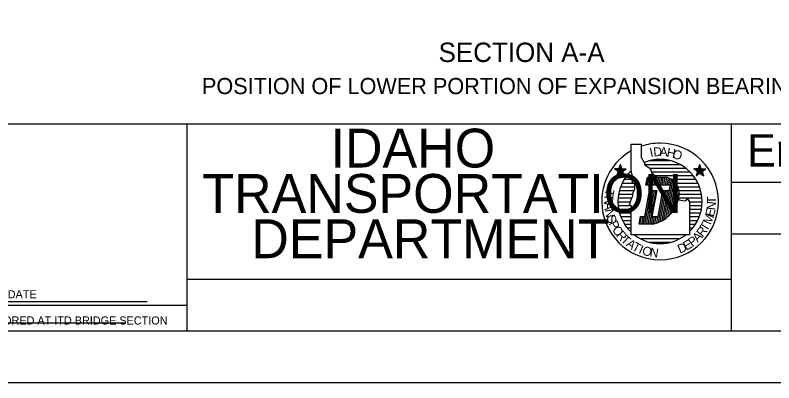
# Model space of a CAD drawing. Extents: x 0 to 22.7, y 0 to 15.7.
# Drawn here: x 8.228 to 13.107, y 0 to 2.366 of the extents above; entities that cross this region are included whole.
import ezdxf

# ---------------------------------------------------------------- set-up
doc = ezdxf.new("R2010")
doc.units = 0
for name, color, linetype in [('BORDER_ANNO_Cutsheet', 7, 'Continuous'), ('BRDG_ANNO_Anno-Large-Print', 7, 'Continuous'), ('BRDG_ANNO_Anno-Sheet', 7, 'Continuous'), ('BRDG_ANNO_Anno-Small-Print', 7, 'Continuous'), ('BRDG_ANNO_General-Notes', 7, 'Continuous')]:
    doc.layers.add(name, color=color, linetype=linetype)

msp = doc.modelspace()

# ---------------------------------------------------------------- linework, layer by layer
at = {"layer": 'BORDER_ANNO_Cutsheet'}
msp.add_lwpolyline([(0, 14.6667), (22.6667, 14.6667), (22.6667, 0), (0, 0)], close=True, dxfattribs=at)
at = {"layer": 'BRDG_ANNO_Anno-Large-Print'}
msp.add_line((7.9329, 0.3871), (8.9371, 0.3871), dxfattribs=at)
at = {"layer": 'BRDG_ANNO_Anno-Sheet'}
for p, q in [((1, 1.6667), (12.8333, 1.6667)), ((9.3333, 0.3333), (9.3333, 1.6667)), ((12.8333, 0.3333), (12.8333, 1.6667)), ((12.8333, 1.6667), (22.3333, 1.6667)), ((12.1896, 1.3617), (12.1896, 1.5354)), ((12.1896, 1.5354), (12.2554, 1.5354)), ((12.2554, 1.4487), (12.2554, 1.5354)), ((12.2554, 1.4487), (12.2729, 1.4175)), ((12.2729, 1.4175), (12.2762, 1.4033)), ((12.31, 1.4296), (12.4387, 1.4296)), ((12.1342, 1.36), (12.0817, 1.3771)), ((12.1104, 1.3771), (12.0817, 1.3771)), ((12.105, 1.36), (12.0817, 1.3771)), ((12.1288, 1.3771), (12.0958, 1.3321)), ((12.105, 1.36), (12.1579, 1.3771)), ((12.1104, 1.3771), (12.1196, 1.4046)), ((12.1104, 1.3771), (12.1433, 1.3321)), ((12.1196, 1.3492), (12.1196, 1.4046)), ((12.1288, 1.3771), (12.1196, 1.4046)), ((12.1288, 1.3771), (12.1579, 1.3771)), ((12.1342, 1.36), (12.1579, 1.3771)), ((12.2762, 1.4033), (12.3108, 1.3792)), ((12.2779, 1.4054), (12.5004, 1.4054)), ((12.31, 1.3817), (12.5379, 1.3817)), ((12.3108, 1.3792), (12.3217, 1.3513)), ((12.645, 1.36), (12.5921, 1.3771)), ((12.6158, 1.36), (12.5921, 1.3771)), ((12.6212, 1.3771), (12.5921, 1.3771)), ((12.6396, 1.3771), (12.6067, 1.3321)), ((12.6158, 1.36), (12.6683, 1.3771)), ((12.6212, 1.3771), (12.6304, 1.4046)), ((12.6212, 1.3771), (12.6542, 1.3321)), ((12.6304, 1.3492), (12.6304, 1.4046)), ((12.6396, 1.3771), (12.6304, 1.4046)), ((12.6396, 1.3771), (12.6683, 1.3771)), ((12.645, 1.36), (12.6683, 1.3771)), ((12.105, 1.36), (12.0958, 1.3321)), ((12.1196, 1.3492), (12.0958, 1.3321)), ((12.1196, 1.3492), (12.1433, 1.3321)), ((12.1342, 1.36), (12.1433, 1.3321)), ((12.1612, 1.3337), (12.1958, 1.3337)), ((12.1829, 1.3575), (12.1908, 1.3575)), ((12.1962, 1.3375), (12.1896, 1.3617)), ((12.1962, 1.3167), (12.1962, 1.3375)), ((12.2833, 1.2712), (12.2937, 1.3237)), ((12.2929, 1.2712), (12.3025, 1.3237)), ((12.2937, 1.3237), (12.4083, 1.3237)), ((12.3033, 1.2712), (12.3133, 1.3237)), ((12.3142, 1.2712), (12.3238, 1.3237)), ((12.3192, 1.3575), (12.5671, 1.3575)), ((12.3217, 1.3513), (12.3562, 1.3237)), ((12.3246, 1.2712), (12.3346, 1.3237)), ((12.335, 1.2712), (12.345, 1.3237)), ((12.3438, 1.3337), (12.5883, 1.3337)), ((12.3458, 1.2712), (12.3554, 1.3237)), ((12.3562, 1.2712), (12.3662, 1.3237)), ((12.3671, 1.2712), (12.3767, 1.3237)), ((12.3775, 1.2712), (12.3875, 1.3237)), ((12.3883, 1.2712), (12.3979, 1.3237)), ((12.3987, 1.2712), (12.4087, 1.3237)), ((12.4092, 1.2712), (12.4187, 1.3208)), ((12.42, 1.2712), (12.4287, 1.3179)), ((12.6158, 1.36), (12.6067, 1.3321)), ((12.6304, 1.3492), (12.6067, 1.3321)), ((12.6304, 1.3492), (12.6542, 1.3321)), ((12.645, 1.36), (12.6542, 1.3321)), ((12.1312, 1.2854), (12.1988, 1.2854)), ((12.1446, 1.3096), (12.195, 1.3096)), ((12.1962, 1.2992), (12.1962, 1.3167)), ((12.2, 1.2854), (12.1962, 1.2992)), ((12.2137, 1.2783), (12.2, 1.2854)), ((12.2137, 1.2608), (12.2137, 1.2783)), ((12.4408, 1.2712), (12.2833, 1.2712)), ((12.3996, 1.0496), (12.4479, 1.3079)), ((12.4117, 1.0571), (12.4575, 1.3013)), ((12.4242, 1.0671), (12.4662, 1.2925)), ((12.4304, 1.2712), (12.4383, 1.3133)), ((12.4346, 1.2367), (12.4408, 1.2712)), ((12.4371, 1.0792), (12.475, 1.2829)), ((12.4458, 1.3096), (12.605, 1.3096)), ((12.4504, 1.0933), (12.4833, 1.2708)), ((12.4733, 1.2854), (12.6183, 1.2854)), ((12.8333, 1.2917), (14.8333, 1.2917)), ((12.1137, 1.2375), (12.2075, 1.2375)), ((12.1208, 1.2617), (12.2125, 1.2617)), ((12.2, 1.2192), (12.2067, 1.2333)), ((12.2067, 1.2333), (12.2137, 1.2504)), ((12.2137, 1.2504), (12.2137, 1.2608)), ((12.2762, 1.07), (12.3075, 1.2367)), ((12.2775, 1.0212), (12.3179, 1.2367)), ((12.2883, 1.0212), (12.3287, 1.2367)), ((12.2988, 1.0212), (12.3392, 1.2367)), ((12.3075, 1.2367), (12.3533, 1.2367)), ((12.3096, 1.0212), (12.35, 1.2367)), ((12.3533, 1.2367), (12.3221, 1.07)), ((12.3625, 1.07), (12.3937, 1.2367)), ((12.3646, 1.0317), (12.4029, 1.2367)), ((12.3758, 1.0367), (12.4133, 1.2367)), ((12.3875, 1.0421), (12.4242, 1.2367)), ((12.3937, 1.2367), (12.4346, 1.2367)), ((12.4646, 1.1125), (12.4912, 1.2546)), ((12.4812, 1.145), (12.4971, 1.23)), ((12.4883, 1.2617), (12.6288, 1.2617)), ((12.4962, 1.2375), (12.6363, 1.2375)), ((12.105, 1.1896), (12.1937, 1.1896)), ((12.1083, 1.2137), (12.1988, 1.2137)), ((12.1858, 1.1671), (12.1896, 1.1812)), ((12.1896, 1.1812), (12.2, 1.2021)), ((12.2, 1.2021), (12.2, 1.2192)), ((12.4938, 1.185), (12.4987, 1.1775)), ((12.495, 1.1896), (12.645, 1.1896)), ((12.4983, 1.2137), (12.6417, 1.2137)), ((12.4987, 1.1775), (12.5196, 1.1742)), ((12.5196, 1.1742), (12.5404, 1.1708)), ((12.5404, 1.1708), (12.5508, 1.1846)), ((12.5508, 1.1846), (12.5646, 1.1638)), ((12.1042, 1.1654), (12.185, 1.1654)), ((12.1054, 1.1417), (12.1875, 1.1417)), ((12.1792, 1.15), (12.1858, 1.1671)), ((12.1896, 1.1396), (12.1792, 1.15)), ((12.1962, 1.1292), (12.1896, 1.1396)), ((12.2, 1.1221), (12.1962, 1.1292)), ((12.5633, 1.1654), (12.6458, 1.1654)), ((12.5646, 1.1638), (12.5646, 0.9517)), ((12.565, 1.1417), (12.6446, 1.1417)), ((12.1087, 1.1175), (12.1988, 1.1175)), ((12.1142, 1.0938), (12.1892, 1.0938)), ((12.1896, 1.1013), (12.2, 1.1117)), ((12.1896, 0.9517), (12.1896, 1.1013)), ((12.2, 1.1117), (12.2, 1.1221)), ((12.5646, 1.1175), (12.6412, 1.1175)), ((12.5646, 1.0938), (12.6358, 1.0938)), ((12.1225, 1.0696), (12.1883, 1.0696)), ((12.1329, 1.0454), (12.1883, 1.0454)), ((12.2396, 1.0212), (12.2487, 1.07)), ((12.2458, 1.0212), (12.255, 1.07)), ((12.2487, 1.07), (12.2762, 1.07)), ((12.2567, 1.0212), (12.2658, 1.07)), ((12.2671, 1.0212), (12.2762, 1.07)), ((12.32, 1.0212), (12.3292, 1.07)), ((12.3221, 1.07), (12.3625, 1.07)), ((12.3308, 1.0217), (12.34, 1.07)), ((12.3421, 1.0246), (12.3504, 1.07)), ((12.3533, 1.0279), (12.3608, 1.07)), ((12.5646, 1.0696), (12.6275, 1.0696)), ((12.5646, 1.0454), (12.6167, 1.0454)), ((12.1467, 1.0217), (12.1887, 1.0217)), ((12.1638, 0.9975), (12.1883, 0.9975)), ((12.3283, 1.0212), (12.2396, 1.0212)), ((12.5646, 1.0217), (12.6033, 1.0217)), ((12.5646, 0.9975), (12.5867, 0.9975)), ((12.185, 0.9738), (12.1892, 0.9738)), ((12.5646, 0.9517), (12.1896, 0.9517)), ((12.5004, 0.9275), (12.2479, 0.9275)), ((12.8333, 0.9583), (14.8333, 0.9583)), ((12.4392, 0.9037), (12.3117, 0.9037)), ((9.3333, 0.6667), (12.8333, 0.6667))]:
    msp.add_line(p, q, dxfattribs=at)
msp.add_lwpolyline([(1, 14.3333), (22.3333, 14.3333), (22.3333, 0.3333), (1, 0.3333)], close=True, dxfattribs=at)
for centre, radius, start, end in [((12.375, 1.1667), 0.375, 90, 108.596), ((12.375, 1.1667), 0.375, 0, 90), ((12.375, 1.1667), 0.375, 119.6331, 180), ((12.375, 1.1667), 0.2708, 90, 112.1452), ((12.375, 1.1667), 0.2708, 0, 90), ((12.375, 1.1667), 0.2708, 133.1926, 180), ((12.3888, 1.2161), 0.1094, 343.4981, 79.7362), ((12.2899, 1.2255), 0.2078, 280.6479, 348.7719), ((12.375, 1.1667), 0.375, 180, 270), ((12.375, 1.1667), 0.2708, 180.2644, 226.7946), ((12.375, 1.1667), 0.375, 270, 0), ((12.375, 1.1667), 0.2708, 314.427, 0), ((12.375, 1.1667), 0.2708, 232.5658, 270), ((12.375, 1.1667), 0.2708, 270, 307.4536)]:
    msp.add_arc(centre, radius, start, end, dxfattribs=at)
at = {"layer": 'BRDG_ANNO_Anno-Small-Print'}
for p, q in [((7.6667, 0.5), (9.3333, 0.5)), ((8.1442, 0.5242), (9.0758, 0.5242))]:
    msp.add_line(p, q, dxfattribs=at)

# ---------------------------------------------------------------- texts
at = {"layer": 'BRDG_ANNO_Anno-Sheet'}
for s, height, p in [('IDAHO', 0.25, (10.2558, 1.3854)), ('English', 0.20833, (12.9337, 1.3912)), ('TRANSPORTATION', 0.25, (9.4313, 1.0938)), ('DEPARTMENT', 0.25, (9.7462, 0.8021))]:
    msp.add_text(s, height=height, dxfattribs=at).set_placement(p)
for s, rotation, p in [('D', 5.2118, (12.3342, 1.4563)), ('A', 357.8718, (12.3712, 1.4587)), ('I', 11.9519, (12.3146, 1.4521)), ('H', 349.6318, (12.4146, 1.4558)), ('O', 342.1917, (12.4496, 1.4487)), ('T', 259.4265, (12.0254, 1.2504)), ('R', 266.0275, (12.0175, 1.205)), ('T', 90.4926, (12.7346, 1.1529)), ('A', 273.764, (12.0154, 1.1604)), ('E', 75.6105, (12.7196, 1.0646)), ('N', 83.1932, (12.73, 1.1087)), ('N', 280.3758, (12.0192, 1.1142)), ('S', 287.9279, (12.0287, 1.0692)), ('M', 67.7139, (12.7004, 1.0137)), ('P', 295.4976, (12.0437, 1.0271)), ('T', 59.0362, (12.6758, 0.97)), ('O', 302.6446, (12.0637, 0.9867)), ('R', 309.9079, (12.0892, 0.9483)), ('R', 52.3344, (12.6492, 0.9342)), ('T', 317.1211, (12.1183, 0.9142)), ('P', 37.6656, (12.5821, 0.8729)), ('A', 45, (12.6171, 0.9004)), ('A', 324.6375, (12.1521, 0.8837)), ('T', 331.7503, (12.1896, 0.8579)), ('I', 337.0213, (12.2329, 0.8358)), ('O', 343.3287, (12.255, 0.8271)), ('D', 22.9887, (12.5021, 0.8304)), ('E', 30.5476, (12.5437, 0.8492)), ('N', 351.6598, (12.3058, 0.8133))]:
    msp.add_text(s, height=0.0579, rotation=rotation, dxfattribs=at).set_placement(p)
at = {"layer": 'BRDG_ANNO_Anno-Small-Print'}
for s, height, p in [('DATE', 0.05248, (8.1792, 0.5437)), ('ORIGINAL STORED AT ITD BRIDGE SECTION', 0.052144, (7.7083, 0.3752))]:
    msp.add_text(s, height=height, dxfattribs=at).set_placement(p)
at = {"layer": 'BRDG_ANNO_General-Notes'}
for s, height, p in [('SECTION A-A', 0.124948, (10.9505, 2.0642)), ('POSITION OF LOWER PORTION OF EXPANSION BEARING', 0.104115, (9.4289, 1.8576))]:
    msp.add_text(s, height=height, dxfattribs=at).set_placement(p)

doc.saveas('drawing.dxf')
